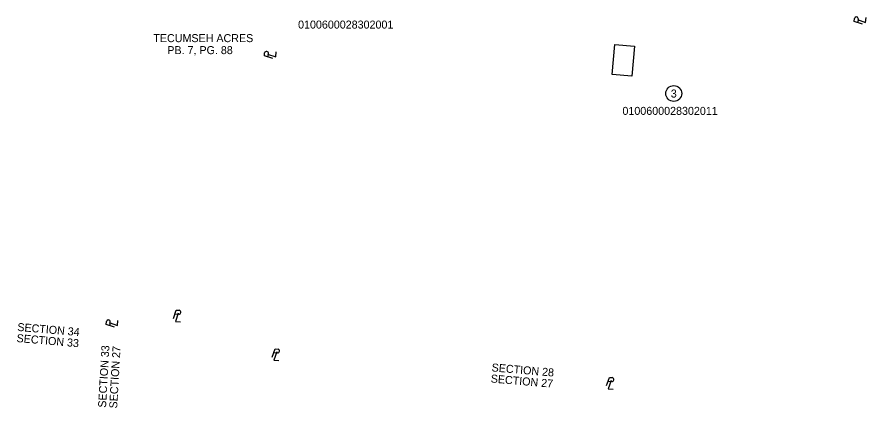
# Model space of a CAD drawing. Extents: x 1571291 to 1576333, y 700252 to 704384.
# Drawn here: x 1571476 to 1574445, y 700401 to 701769 of the extents above; entities that cross this region are included whole.
import ezdxf

# ---------------------------------------------------------------- set-up
doc = ezdxf.new("R2010")
doc.units = 0
doc.layers.add('RW_X_CL_100_Bearings', color=7, linetype='Continuous')
doc.layers.add('RW_X_CL_100_Cardinal_Points', color=7, linetype='Continuous')

msp = doc.modelspace()

# ---------------------------------------------------------------- linework, layer by layer
at = {"layer": 'RW_X_CL_100_Bearings'}
msp.add_lwpolyline([(1573635.4, 701667.6), (1573626.5, 701561.9), (1573557.8, 701567.7), (1573566.7, 701673.4)], close=True, dxfattribs=at)
msp.add_circle((1573772.7, 701501.4), 27.7, dxfattribs=at)
at = {"layer": 'RW_X_CL_100_Cardinal_Points'}
for p, q in [((1574417.3, 701749), (1574418.2, 701762)), ((1574424.1, 701756.6), (1574424.1, 701756.6)), ((1572355.2, 701628.6), (1572356, 701641.6)), ((1572361.9, 701636.3), (1572361.9, 701636.3)), ((1571801.9, 700689.2), (1571802.7, 700702.1)), ((1572029.1, 700730.2), (1572042, 700729.5)), ((1572036.7, 700723.5), (1572036.7, 700723.5)), ((1571808.6, 700696.8), (1571808.6, 700696.8)), ((1572374.1, 700595), (1572387, 700593.9)), ((1572381.5, 700588.1), (1572381.5, 700588.1)), ((1573542.8, 700495.3), (1573555.7, 700494.2)), ((1573550.3, 700488.4), (1573550.3, 700488.4))]:
    msp.add_line(p, q, dxfattribs=at)
for points in [[(1574432.9, 701743.7), (1574403.9, 701753.7), (1574404.6, 701764)], [(1574414.7, 701759.9), (1574443.6, 701749.9), (1574444.9, 701767.3)], [(1572370.9, 701623.5), (1572341.7, 701633), (1572342.3, 701643.3)], [(1572352.5, 701639.5), (1572381.6, 701629.9), (1572382.5, 701647.4)], [(1572024, 700714.5), (1572033.5, 700743.7), (1572043.8, 700743.1)], [(1572039.9, 700732.9), (1572030.4, 700703.9), (1572047.8, 700702.9)], [(1571817.6, 700684.1), (1571788.4, 700693.6), (1571789, 700703.9)], [(1571799.2, 700700), (1571828.3, 700690.5), (1571829.2, 700707.9)], [(1572368.5, 700579.5), (1572378.8, 700608.4), (1572389.1, 700607.5)], [(1572385, 700597.5), (1572374.6, 700568.7), (1572392, 700567.2)], [(1573537.3, 700479.8), (1573547.6, 700508.6), (1573557.9, 700507.7)], [(1573553.7, 700497.7), (1573543.3, 700468.9), (1573560.7, 700467.4)]]:
    msp.add_lwpolyline(points, dxfattribs=at)
for centre, start, end in [((1574411.4, 701762.4), 356.2728, 167.1299), ((1572349.1, 701641.9), 357.2712, 168.1283), ((1572042.4, 700736.3), 267.2712, 78.1283), ((1571795.8, 700702.5), 357.2712, 168.1283), ((1572387.5, 700600.8), 265.593, 76.4501), ((1573556.2, 700501), 265.593, 76.4501)]:
    msp.add_arc(centre, 6.9, start, end, dxfattribs=at)

# ---------------------------------------------------------------- texts
at = {"layer": 'RW_X_CL_100_Bearings'}
for s, p in [('0100600028302001', (1572459.2, 701728.7)), ('TECUMSEH ACRES', (1571953.1, 701681.3)), ('PB. 7, PG. 88', (1572002, 701639.3)), ('3', (1573762.3, 701487.4)), ('0100600028302011', (1573593.3, 701426.8))]:
    msp.add_text(s, height=28, dxfattribs=at).set_placement(p)
for s, rotation, p in [('SECTION 34', 355.122, (1571476.7, 700671.3)), ('SECTION 33', 355.122, (1571474.2, 700632.3)), ('SECTION 33', 86.8002, (1571787.7, 700401.8)), ('SECTION 27', 86.8002, (1571826.6, 700399.2)), ('SECTION 28', 355.122, (1573135.1, 700529.7)), ('SECTION 27', 355.122, (1573131.9, 700490.8))]:
    msp.add_text(s, height=28, rotation=rotation, dxfattribs=at).set_placement(p)

doc.saveas('drawing.dxf')
